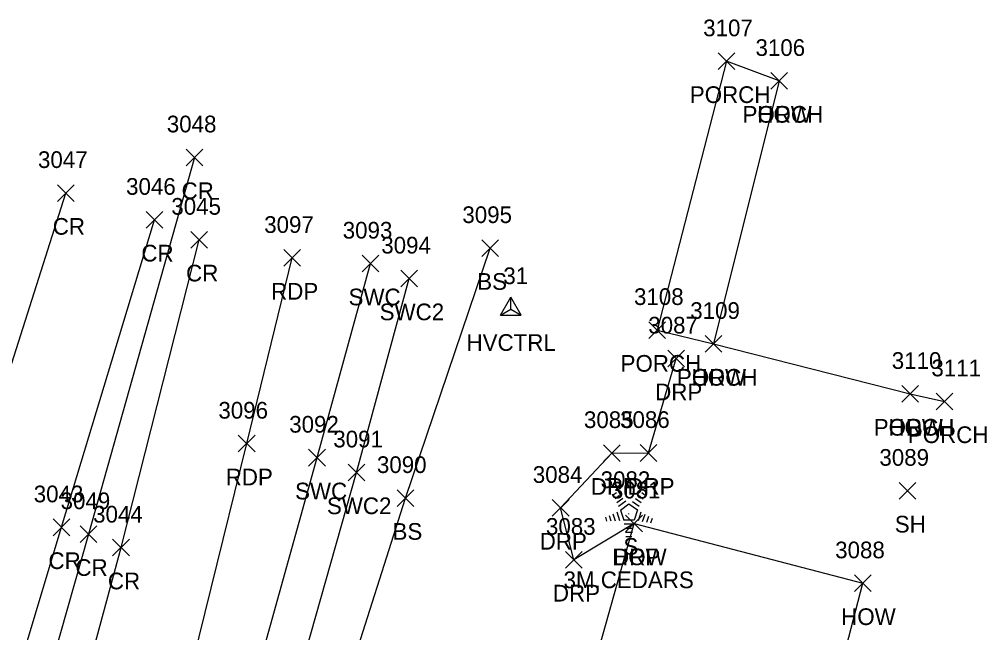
# Model space of a CAD drawing. Extents: x 1477930 to 1480780, y 774090 to 784647.
# Drawn here: x 1479566.7 to 1479682.6, y 775250.7 to 775324.2 of the extents above; entities that cross this region are included whole.
import ezdxf

# ---------------------------------------------------------------- set-up
doc = ezdxf.new("R2010")
doc.units = 0
for name, color, linetype in [('C_A', 7, 'Continuous'), ('C_I', 7, 'Continuous'), ('CPSM', 7, 'Continuous'), ('L_A', 7, 'Continuous'), ('L_C', 7, 'Continuous'), ('L_I', 7, 'Continuous'), ('L_TIC', 7, 'Continuous'), ('LBC', 7, 'Continuous'), ('LBF', 7, 'Continuous'), ('LELB', 7, 'Continuous'), ('LTC', 7, 'Continuous'), ('P_A', 7, 'Continuous'), ('P_I', 7, 'Continuous'), ('P_TIC', 7, 'Continuous'), ('PET', 7, 'Continuous'), ('PRC', 7, 'Continuous'), ('R_A', 7, 'Continuous'), ('R_I', 7, 'Continuous'), ('R_TIC', 7, 'Continuous'), ('RDP', 7, 'Continuous'), ('RSW', 7, 'Continuous')]:
    doc.layers.add(name, color=color, linetype=linetype)

msp = doc.modelspace()

# ---------------------------------------------------------------- linework, layer by layer
at = {"layer": 'CPSM'}
for p, q in [((1479624.37, 775288.74), (1479625.62, 775290.9)), ((1479626.87, 775288.74), (1479625.62, 775290.9)), ((1479625.62, 775289.46), (1479625.62, 775290.9)), ((1479624.37, 775288.74), (1479625.62, 775289.46)), ((1479625.62, 775289.46), (1479625.62, 775289.46)), ((1479625.62, 775289.46), (1479626.87, 775288.74)), ((1479624.37, 775288.74), (1479626.87, 775288.74))]:
    msp.add_line(p, q, dxfattribs=at)
at = {"layer": 'L_TIC'}
for points in [[(1479650.45, 775318.17), (1479652.45, 775320.17)], [(1479652.45, 775318.17), (1479650.45, 775320.17)], [(1479656.77, 775315.81), (1479658.77, 775317.81)], [(1479658.77, 775315.81), (1479656.77, 775317.81)], [(1479656.77, 775315.81), (1479658.77, 775317.81)], [(1479658.77, 775315.81), (1479656.77, 775317.81)], [(1479622.15, 775295.78), (1479624.15, 775297.78)], [(1479624.15, 775295.78), (1479622.15, 775297.78)], [(1479642.15, 775285.96), (1479644.15, 775287.96)], [(1479644.15, 775285.96), (1479642.15, 775287.96)], [(1479648.9, 775284.29), (1479650.9, 775286.29)], [(1479650.9, 775284.29), (1479648.9, 775286.29)], [(1479648.9, 775284.29), (1479650.9, 775286.29)], [(1479650.9, 775284.29), (1479648.9, 775286.29)], [(1479672.49, 775278.3), (1479674.49, 775280.3)], [(1479674.49, 775278.3), (1479672.49, 775280.3)], [(1479672.49, 775278.3), (1479674.49, 775280.3)], [(1479674.49, 775278.3), (1479672.49, 775280.3)], [(1479676.58, 775277.41), (1479678.58, 775279.41)], [(1479678.58, 775277.41), (1479676.58, 775279.41)], [(1479672.14, 775266.69), (1479674.14, 775268.69)], [(1479674.14, 775266.69), (1479672.14, 775268.69)], [(1479611.99, 775265.82), (1479613.99, 775267.82)], [(1479613.99, 775265.82), (1479611.99, 775267.82)], [(1479639.38, 775262.77), (1479641.38, 775264.77)], [(1479641.38, 775262.77), (1479639.38, 775264.77)], [(1479666.82, 775255.6), (1479668.82, 775257.6)], [(1479668.82, 775255.6), (1479666.82, 775257.6)], [(1479666.82, 775255.6), (1479668.82, 775257.6)], [(1479668.82, 775255.6), (1479666.82, 775257.6)]]:
    msp.add_lwpolyline(points, dxfattribs=at)
at = {"layer": 'LBC'}
for points in [[(1479657.77, 775316.81), (1479649.9, 775285.29), (1479673.49, 775279.3)], [(1479647.59, 775178.63), (1479641.99, 775180.15), (1479618.79, 775185.79), (1479625.93, 775209.89), (1479629.39, 775222.28), (1479633.62, 775239.59), (1479640.38, 775263.77), (1479667.82, 775256.6)], [(1479647.59, 775178.63), (1479667.82, 775256.6)]]:
    msp.add_lwpolyline(points, dxfattribs=at)
at = {"layer": 'LBF'}
for points in [[(1479657.77, 775316.81), (1479651.45, 775319.17), (1479643.15, 775286.96), (1479649.9, 775285.29)], [(1479673.49, 775279.3), (1479677.58, 775278.41)]]:
    msp.add_lwpolyline(points, dxfattribs=at)
at = {"layer": 'LELB'}
msp.add_lwpolyline([(1479585.89, 775194.46), (1479590.06, 775195.88), (1479599.23, 775202.42), (1479600.85, 775208.61), (1479605.91, 775244.6), (1479612.99, 775266.82), (1479623.15, 775296.78)], dxfattribs=at)
at = {"layer": 'LTC'}
for p, q in [((1479637.91, 775267.23), (1479638.27, 775267.49)), ((1479641.31, 775267.47), (1479641.73, 775267.16)), ((1479638.12, 775266.76), (1479638.65, 775267.15)), ((1479638.33, 775266.3), (1479639.04, 775266.81)), ((1479638.54, 775265.83), (1479639.42, 775266.47)), ((1479640.2, 775266.42), (1479641.01, 775265.83)), ((1479640.57, 775266.77), (1479641.25, 775266.28)), ((1479640.94, 775267.12), (1479641.49, 775266.72)), ((1479638.31, 775265.16), (1479638.64, 775264.14)), ((1479638.77, 775265.38), (1479639.78, 775266.11)), ((1479638.77, 775265.38), (1479639.15, 775264.18)), ((1479639.78, 775266.11), (1479640.78, 775265.39)), ((1479640.78, 775265.39), (1479640.39, 775264.18)), ((1479641.21, 775265.11), (1479640.88, 775264.07)), ((1479636.95, 775264.51), (1479637.1, 775264.04)), ((1479637.4, 775264.72), (1479637.61, 775264.07)), ((1479637.86, 775264.94), (1479638.13, 775264.1)), ((1479640.39, 775264.18), (1479639.15, 775264.18)), ((1479641.66, 775264.86), (1479641.37, 775263.98)), ((1479642.1, 775264.61), (1479641.87, 775263.88)), ((1479642.55, 775264.36), (1479642.36, 775263.79)), ((1479640.35, 775263.68), (1479639.2, 775263.68)), ((1479640.26, 775263.18), (1479639.27, 775263.18)), ((1479640.18, 775262.68), (1479639.35, 775262.68)), ((1479640.1, 775262.18), (1479639.42, 775262.18))]:
    msp.add_line(p, q, dxfattribs=at)
at = {"layer": 'P_TIC'}
for points in [[(1479586.72, 775306.65), (1479588.72, 775308.65)], [(1479588.72, 775306.65), (1479586.72, 775308.65)], [(1479571.29, 775302.38), (1479573.29, 775304.38)], [(1479573.29, 775302.38), (1479571.29, 775304.38)], [(1479581.9, 775299.17), (1479583.9, 775301.17)], [(1479583.9, 775299.17), (1479581.9, 775301.17)], [(1479587.27, 775296.78), (1479589.27, 775298.78)], [(1479589.27, 775296.78), (1479587.27, 775298.78)], [(1479598.4, 775294.6), (1479600.4, 775296.6)], [(1479600.4, 775294.6), (1479598.4, 775296.6)], [(1479592.96, 775272.34), (1479594.96, 775274.34)], [(1479594.96, 775272.34), (1479592.96, 775274.34)], [(1479570.78, 775262.31), (1479572.78, 775264.31)], [(1479572.78, 775262.31), (1479570.78, 775264.31)], [(1479574.01, 775261.49), (1479576.01, 775263.49)], [(1479576.01, 775261.49), (1479574.01, 775263.49)], [(1479577.9, 775259.88), (1479579.9, 775261.88)], [(1479579.9, 775259.88), (1479577.9, 775261.88)]]:
    msp.add_lwpolyline(points, dxfattribs=at)
at = {"layer": 'PET'}
msp.add_lwpolyline([(1479231.31, 774636.06), (1479272.54, 774672.78), (1479302.99, 774702.6), (1479344.22, 774746.86), (1479373.44, 774780.01), (1479405.23, 774818.27), (1479428.23, 774848.68), (1479447.93, 774875.75), (1479460.71, 774894.51), (1479479.69, 774925.18), (1479480.31, 774927.38), (1479493.45, 774951.2), (1479514.74, 775006.53), (1479531.7, 775055.13), (1479548.14, 775106.72), (1479553.83, 775125.43), (1479564.45, 775161.29), (1479573.74, 775193.3), (1479576.58, 775204.25), (1479585.43, 775238.68), (1479593.96, 775273.34), (1479599.4, 775295.6)], dxfattribs=at)
at = {"layer": 'PRC'}
for points in [[(1479587.72, 775307.65), (1479575.01, 775262.49), (1479563.12, 775220.83), (1479548.57, 775168.37), (1479533.5, 775112.54), (1479513.76, 775053.7)], [(1479510.93, 775118.31), (1479531.61, 775174.16), (1479544.79, 775215.47), (1479560.12, 775265.14), (1479572.29, 775303.38)], [(1479430.01, 774890.62), (1479468.91, 774957.83), (1479493.21, 775011.92), (1479503.06, 775052.08), (1479530.4, 775123.25), (1479541.54, 775166.06), (1479555.58, 775209.55), (1479571.78, 775263.31), (1479582.9, 775300.17)], [(1479438.76, 774885), (1479466.69, 774929.85), (1479479.06, 774955.89), (1479501.08, 775005.62), (1479520.94, 775059.64), (1479540.23, 775118.92), (1479552.22, 775163.96), (1479564.07, 775206.06), (1479578.9, 775260.88), (1479588.27, 775297.78)]]:
    msp.add_lwpolyline(points, dxfattribs=at)
at = {"layer": 'R_TIC'}
for points in [[(1479607.81, 775293.92), (1479609.81, 775295.92)], [(1479609.81, 775293.92), (1479607.81, 775295.92)], [(1479612.43, 775292.13), (1479614.43, 775294.13)], [(1479614.43, 775292.13), (1479612.43, 775294.13)], [(1479644.43, 775282.54), (1479646.43, 775284.54)], [(1479646.43, 775282.54), (1479644.43, 775284.54)], [(1479636.72, 775271.21), (1479638.72, 775273.21)], [(1479638.72, 775271.21), (1479636.72, 775273.21)], [(1479641.1, 775271.22), (1479643.1, 775273.22)], [(1479643.1, 775271.22), (1479641.1, 775273.22)], [(1479601.39, 775270.66), (1479603.39, 775272.66)], [(1479603.39, 775270.66), (1479601.39, 775272.66)], [(1479606.11, 775268.89), (1479608.11, 775270.89)], [(1479608.11, 775268.89), (1479606.11, 775270.89)], [(1479630.59, 775264.64), (1479632.59, 775266.64)], [(1479632.59, 775264.64), (1479630.59, 775266.64)], [(1479639.38, 775262.77), (1479641.38, 775264.77)], [(1479641.38, 775262.77), (1479639.38, 775264.77)], [(1479632.17, 775258.42), (1479634.17, 775260.42)], [(1479634.17, 775258.42), (1479632.17, 775260.42)]]:
    msp.add_lwpolyline(points, dxfattribs=at)
at = {"layer": 'RDP'}
msp.add_lwpolyline([(1479640.38, 775263.77), (1479633.17, 775259.42), (1479631.59, 775265.64), (1479637.72, 775272.21), (1479642.1, 775272.22), (1479645.43, 775283.54)], dxfattribs=at)
at = {"layer": 'RSW'}
for points in [[(1479580.51, 775203.37), (1479583.22, 775202.73), (1479594.67, 775243.82), (1479602.39, 775271.66), (1479608.81, 775294.92)], [(1479579.19, 775198.63), (1479586.42, 775196.76), (1479607.11, 775269.89), (1479613.43, 775293.13)]]:
    msp.add_lwpolyline(points, dxfattribs=at)

# ---------------------------------------------------------------- texts
at = {"layer": 'C_A'}
msp.add_text('HVCTRL', height=2, dxfattribs=at).set_placement((1479620.31, 775284.46))
at = {"layer": 'C_I'}
msp.add_text('31', height=2, dxfattribs=at).set_placement((1479624.72, 775292.46))
at = {"layer": 'L_A'}
for s, p in [('PORCH', (1479647.07, 775314.17)), ('PORCH', (1479653.39, 775311.81)), ('HOW', (1479655.16, 775311.81)), ('BS', (1479621.59, 775291.78)), ('PORCH', (1479638.77, 775281.96)), ('PORCH', (1479645.52, 775280.29)), ('HOW', (1479647.28, 775280.29)), ('PORCH', (1479669.11, 775274.3)), ('HOW', (1479670.87, 775274.3)), ('PORCH', (1479673.2, 775273.41)), ('SH', (1479671.63, 775262.69)), ('BS', (1479611.44, 775261.82)), ('S', (1479639.11, 775260.02)), ('HOW', (1479637.76, 775258.77)), ('HOW', (1479665.21, 775251.6)), ('HOW', (1479665.21, 775251.6))]:
    msp.add_text(s, height=2, dxfattribs=at).set_placement(p)
at = {"layer": 'L_C'}
msp.add_text('3M.CEDARS', height=2, dxfattribs=at).set_placement((1479631.94, 775256.02))
at = {"layer": 'L_I'}
for s, p in [('3107', (1479648.67, 775322.17)), ('3106', (1479654.94, 775319.81)), ('3106', (1479654.94, 775319.81)), ('3095', (1479619.81, 775299.78)), ('3108', (1479640.38, 775289.96)), ('3109', (1479647.12, 775288.29)), ('3109', (1479647.12, 775288.29)), ('3110', (1479671.27, 775282.3)), ('3110', (1479671.27, 775282.3)), ('3111', (1479676.02, 775281.41)), ('3089', (1479669.79, 775270.69)), ('3090', (1479609.57, 775269.82)), ('3082', (1479636.38, 775268.02)), ('3081', (1479637.61, 775266.77)), ('3088', (1479664.49, 775259.6)), ('3088', (1479664.49, 775259.6))]:
    msp.add_text(s, height=2, dxfattribs=at).set_placement(p)
at = {"layer": 'LTC'}
msp.add_text('.', height=1.04, rotation=270, dxfattribs=at).set_placement((1479639.66, 775265.12))
at = {"layer": 'P_A'}
for s, p in [('CR', (1479586.16, 775302.65)), ('CR', (1479570.72, 775298.38)), ('CR', (1479581.34, 775295.17)), ('CR', (1479586.7, 775292.78)), ('RDP', (1479596.89, 775290.6)), ('RDP', (1479591.45, 775268.34)), ('CR', (1479570.21, 775258.31)), ('CR', (1479573.44, 775257.49)), ('CR', (1479577.33, 775255.88))]:
    msp.add_text(s, height=2, dxfattribs=at).set_placement(p)
at = {"layer": 'P_I'}
for s, p in [('3048', (1479584.39, 775310.65)), ('3047', (1479568.95, 775306.38)), ('3046', (1479579.51, 775303.17)), ('3045', (1479584.93, 775300.78)), ('3097', (1479596.06, 775298.6)), ('3096', (1479590.57, 775276.34)), ('3043', (1479568.44, 775266.31)), ('3049', (1479571.66, 775265.49)), ('3044', (1479575.56, 775263.88))]:
    msp.add_text(s, height=2, dxfattribs=at).set_placement(p)
at = {"layer": 'R_A'}
for s, p in [('SWC', (1479606.17, 775289.92)), ('SWC2', (1479609.9, 775288.13)), ('DRP', (1479642.92, 775278.54)), ('SWC', (1479599.76, 775266.66)), ('DRP', (1479635.21, 775267.21)), ('DRP', (1479639.59, 775267.22)), ('SWC2', (1479603.58, 775264.89)), ('DRP', (1479629.08, 775260.64)), ('DRP', (1479637.87, 775258.77)), ('DRP', (1479630.66, 775254.42))]:
    msp.add_text(s, height=2, dxfattribs=at).set_placement(p)
at = {"layer": 'R_I'}
for s, p in [('3093', (1479605.47, 775297.92)), ('3094', (1479610.09, 775296.13)), ('3087', (1479642.09, 775286.54)), ('3092', (1479599.06, 775274.66)), ('3085', (1479634.38, 775275.21)), ('3086', (1479638.71, 775275.22)), ('3091', (1479604.34, 775272.89)), ('3084', (1479628.25, 775268.64)), ('3081', (1479637.61, 775266.77)), ('3083', (1479629.83, 775262.42))]:
    msp.add_text(s, height=2, dxfattribs=at).set_placement(p)

doc.saveas('drawing.dxf')
